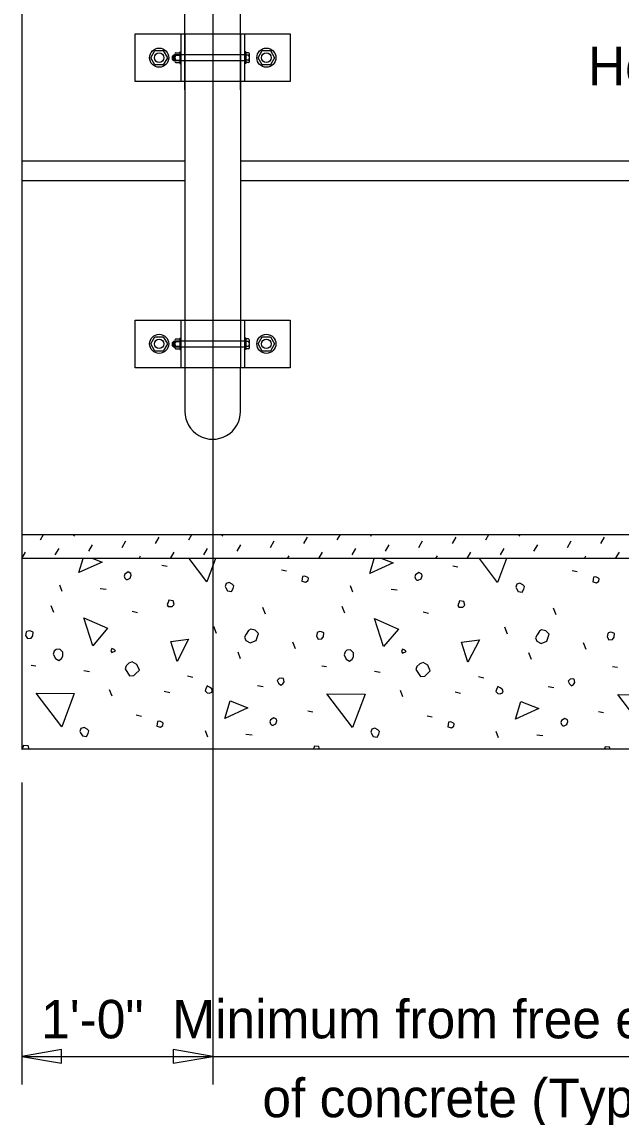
# Model space of a CAD drawing. Extents: x 0 to 41, y -96 to 25.
# Drawn here: x 4.32 to 7.46, y 9.59 to 15.33 of the extents above; entities that cross this region are included whole.
import ezdxf

# ---------------------------------------------------------------- set-up
doc = ezdxf.new("R2010")
doc.units = 0
for name, color, linetype in [('CL_Major', 7, 'Continuous'), ('Dimension', 7, 'Continuous'), ('Miscellaneous', 7, 'Continuous'), ('SteelMisc', 7, 'Continuous'), ('SteelMisc_h', 7, 'Continuous'), ('SupstrConc', 7, 'Continuous'), ('TextStructures', 7, 'Continuous')]:
    doc.layers.add(name, color=color, linetype=linetype)

msp = doc.modelspace()

# ---------------------------------------------------------------- linework, layer by layer
at = {"layer": 'CL_Major'}
msp.add_line((5.3237, 24.7173), (5.3237, 9.756), dxfattribs=at)
at = {"layer": 'Dimension'}
for p, q in [((4.3237, 11.3401), (4.3237, 9.756)), ((4.3238, 9.9041), (9.0982, 9.9041))]:
    msp.add_line(p, q, dxfattribs=at)
for points in [[(4.3238, 9.9041), (4.532, 9.8688), (4.532, 9.9394)], [(5.3238, 9.9042), (5.1155, 9.9395), (5.1155, 9.8689)]]:
    msp.add_lwpolyline(points, close=True, dxfattribs=at)
at = {"layer": 'Miscellaneous'}
for p, q in [((5.1162, 15.1316), (5.1162, 15.1437)), ((5.1219, 15.1316), (5.1219, 15.1437)), ((5.1162, 13.6316), (5.1162, 13.6437)), ((5.1219, 13.6316), (5.1219, 13.6437)), ((4.421, 12.6107), (4.437, 12.6385)), ((4.596, 12.6302), (4.6008, 12.6385)), ((5.1988, 12.6107), (5.2148, 12.6385)), ((5.3738, 12.6302), (5.3786, 12.6385)), ((5.9766, 12.6107), (5.9927, 12.6385)), ((6.1516, 12.6302), (6.1564, 12.6385)), ((6.7544, 12.6107), (6.7705, 12.6385)), ((6.9294, 12.6302), (6.9342, 12.6385)), ((4.6738, 12.5524), (4.6932, 12.586)), ((4.8488, 12.5718), (4.8682, 12.6054)), ((5.0238, 12.5913), (5.0432, 12.6249)), ((5.4516, 12.5524), (5.471, 12.586)), ((5.6266, 12.5718), (5.646, 12.6054)), ((5.8016, 12.5913), (5.821, 12.6249)), ((6.2294, 12.5524), (6.2488, 12.586)), ((6.4044, 12.5718), (6.4238, 12.6054)), ((6.5794, 12.5913), (6.5989, 12.6249)), ((7.0072, 12.5524), (7.0267, 12.586)), ((7.1822, 12.5718), (7.2017, 12.6054)), ((7.3572, 12.5913), (7.3767, 12.6249)), ((4.3237, 12.5135), (4.3432, 12.5471)), ((4.4987, 12.533), (4.5182, 12.5665)), ((4.9378, 12.5135), (4.946, 12.5276)), ((5.1016, 12.5135), (5.121, 12.5471)), ((5.2766, 12.533), (5.296, 12.5665)), ((5.7156, 12.5135), (5.7238, 12.5276)), ((5.8794, 12.5135), (5.8988, 12.5471)), ((6.0544, 12.533), (6.0738, 12.5665)), ((6.4934, 12.5135), (6.5016, 12.5276)), ((6.6572, 12.5135), (6.6766, 12.5471)), ((6.8322, 12.533), (6.8516, 12.5665)), ((7.2713, 12.5135), (7.2794, 12.5276)), ((7.435, 12.5135), (7.4545, 12.5471)), ((5.0576, 12.4782), (5.0841, 12.4728)), ((6.5814, 12.4746), (6.6079, 12.4693)), ((5.6833, 12.4534), (5.7099, 12.4481)), ((7.2072, 12.4499), (7.2337, 12.4446)), ((4.5343, 12.3403), (4.5219, 12.3739)), ((4.7341, 12.3562), (4.7659, 12.3526)), ((6.0581, 12.3367), (6.0457, 12.3703)), ((6.2579, 12.3526), (6.2897, 12.3491)), ((4.4919, 12.2307), (4.4777, 12.266)), ((4.902, 12.2377), (4.9303, 12.2307)), ((5.6003, 12.2218), (5.5861, 12.2572)), ((6.0157, 12.2271), (6.0015, 12.2625)), ((6.4258, 12.2342), (6.4541, 12.2271)), ((7.1241, 12.2183), (7.1099, 12.2536)), ((5.3439, 12.1211), (5.3298, 12.1564)), ((6.8677, 12.1175), (6.8536, 12.1529)), ((5.7576, 12.0397), (5.7434, 12.0751)), ((7.2814, 12.0362), (7.2673, 12.0716)), ((5.4694, 11.9885), (5.4571, 12.0221)), ((6.9933, 11.9849), (6.9809, 12.0185)), ((4.3717, 11.9549), (4.3964, 11.9514)), ((5.8955, 11.9514), (5.9202, 11.9478)), ((7.4193, 11.9478), (7.444, 11.9443)), ((4.6474, 11.9266), (4.6775, 11.9213)), ((5.1919, 11.8983), (5.2202, 11.8913)), ((6.1712, 11.9231), (6.2013, 11.9178)), ((6.7157, 11.8948), (6.744, 11.8877)), ((4.7959, 11.7923), (4.7835, 11.8258)), ((5.5578, 11.8471), (5.5879, 11.8418)), ((7.0816, 11.8435), (7.1117, 11.8382)), ((5.0699, 11.8188), (5.0982, 11.8117)), ((6.3197, 11.7887), (6.3074, 11.8223)), ((6.5937, 11.8152), (6.622, 11.8082)), ((4.3237, 11.7127), (4.3239, 11.7127)), ((5.8212, 11.7145), (5.8477, 11.7092)), ((7.345, 11.7109), (7.3716, 11.7056)), ((4.9232, 11.6933), (4.9497, 11.688)), ((6.447, 11.6897), (6.4735, 11.6844)), ((5.298, 11.5766), (5.2856, 11.6102)), ((6.8218, 11.5731), (6.8094, 11.6066)), ((5.4977, 11.5925), (5.5295, 11.589)), ((7.0215, 11.589), (7.0534, 11.5854))]:
    msp.add_line(p, q, dxfattribs=at)
for points in [[(4.6227, 12.4393), (4.6455, 12.5135)], [(4.6956, 12.5135), (4.7447, 12.4941), (4.6227, 12.4393)], [(5.2927, 12.3915), (5.2, 12.5135)], [(5.3383, 12.5135), (5.2927, 12.3915)], [(6.1465, 12.4357), (6.1704, 12.5135)], [(6.2105, 12.5135), (6.2685, 12.4905), (6.1465, 12.4357)], [(6.8165, 12.388), (6.7211, 12.5135)], [(6.8634, 12.5135), (6.8165, 12.388)], [(4.8702, 12.4039), (4.8772, 12.4039), (4.8914, 12.411), (4.8967, 12.4269), (4.8949, 12.4357), (4.8808, 12.4428), (4.8631, 12.4322), (4.8596, 12.4216), (4.8631, 12.411), (4.8702, 12.4039)], [(5.7912, 12.3951), (5.8106, 12.3898), (5.823, 12.3986), (5.8248, 12.411), (5.8212, 12.4145), (5.8071, 12.4216), (5.7947, 12.4198), (5.7929, 12.4074), (5.7912, 12.3951)], [(6.394, 12.4004), (6.4011, 12.4004), (6.4152, 12.4074), (6.4205, 12.4234), (6.4187, 12.4322), (6.4046, 12.4393), (6.3869, 12.4287), (6.3834, 12.418), (6.3869, 12.4074), (6.394, 12.4004)], [(7.315, 12.3915), (7.3344, 12.3862), (7.3468, 12.3951), (7.3486, 12.4074), (7.345, 12.411), (7.3309, 12.418), (7.3185, 12.4163), (7.3168, 12.4039), (7.315, 12.3915)], [(5.3917, 12.3597), (5.4005, 12.3438), (5.4217, 12.3403), (5.4306, 12.3562), (5.4341, 12.3703), (5.4252, 12.3792), (5.4093, 12.388), (5.3934, 12.3827), (5.3881, 12.3668), (5.3917, 12.3597)], [(6.9155, 12.3562), (6.9243, 12.3403), (6.9455, 12.3367), (6.9544, 12.3526), (6.9579, 12.3668), (6.9491, 12.3756), (6.9332, 12.3845), (6.9172, 12.3792), (6.9119, 12.3632), (6.9155, 12.3562)], [(5.0894, 12.2625), (5.1106, 12.2625), (5.1212, 12.2731), (5.1159, 12.2925), (5.0929, 12.2943), (5.0894, 12.2837), (5.0841, 12.2749), (5.0894, 12.2625), (5.0858, 12.266)], [(6.6132, 12.2589), (6.6344, 12.2589), (6.645, 12.2696), (6.6397, 12.289), (6.6167, 12.2908), (6.6132, 12.2802), (6.6079, 12.2713), (6.6132, 12.2589), (6.6097, 12.2625)], [(4.6952, 12.0557), (4.6474, 12.2024), (4.7729, 12.1476), (4.6952, 12.0557)], [(6.219, 12.0521), (6.1712, 12.1988), (6.2968, 12.144), (6.219, 12.0521)], [(4.3434, 12.1105), (4.3522, 12.0945), (4.3717, 12.0963), (4.3805, 12.1087), (4.3823, 12.1281), (4.3699, 12.1334), (4.3611, 12.1352), (4.3504, 12.1317), (4.3469, 12.1281), (4.3434, 12.1105)], [(5.4977, 12.0839), (5.5207, 12.0716), (5.5508, 12.0839), (5.5631, 12.1211), (5.5455, 12.1387), (5.5225, 12.144), (5.5119, 12.137), (5.4995, 12.1175), (5.4907, 12.1016), (5.4977, 12.0839)], [(5.8672, 12.1069), (5.876, 12.091), (5.8955, 12.0928), (5.9043, 12.1052), (5.9061, 12.1246), (5.8937, 12.1299), (5.8849, 12.1317), (5.8743, 12.1281), (5.8707, 12.1246), (5.8672, 12.1069)], [(7.0215, 12.0804), (7.0445, 12.068), (7.0746, 12.0804), (7.0869, 12.1175), (7.0693, 12.1352), (7.0463, 12.1405), (7.0357, 12.1334), (7.0233, 12.114), (7.0145, 12.0981), (7.0215, 12.0804)], [(7.391, 12.1034), (7.3998, 12.0875), (7.4193, 12.0892), (7.4281, 12.1016), (7.4299, 12.1211), (7.4175, 12.1264), (7.4087, 12.1281), (7.3981, 12.1246), (7.3945, 12.1211), (7.391, 12.1034)], [(5.1371, 11.9743), (5.1035, 12.0786), (5.1972, 12.091), (5.1371, 11.9743)], [(6.6609, 11.9708), (6.6273, 12.0751), (6.721, 12.0875), (6.6609, 11.9708)], [(4.4883, 12.0115), (4.4989, 11.9902), (4.5166, 11.9796), (4.5308, 11.9902), (4.5378, 12.0009), (4.5378, 12.0221), (4.5219, 12.038), (4.5025, 12.0362), (4.4936, 12.0274), (4.4883, 12.0115)], [(4.7942, 12.0203), (4.8136, 12.0291), (4.8065, 12.0362), (4.7942, 12.0415), (4.7889, 12.0291), (4.7942, 12.0203)], [(6.0121, 12.0079), (6.0228, 11.9867), (6.0404, 11.9761), (6.0546, 11.9867), (6.0616, 11.9973), (6.0616, 12.0185), (6.0457, 12.0344), (6.0263, 12.0327), (6.0174, 12.0238), (6.0121, 12.0079)], [(6.318, 12.0168), (6.3374, 12.0256), (6.3303, 12.0327), (6.318, 12.038), (6.3127, 12.0256), (6.318, 12.0168)], [(4.8649, 11.9354), (4.8878, 11.8983), (4.9108, 11.9001), (4.9197, 11.9089), (4.9391, 11.9284), (4.9267, 11.9584), (4.902, 11.9726), (4.8843, 11.9655), (4.8702, 11.9514), (4.8649, 11.9354)], [(6.3887, 11.9319), (6.4117, 11.8948), (6.4346, 11.8966), (6.4435, 11.9054), (6.4629, 11.9248), (6.4506, 11.9549), (6.4258, 11.969), (6.4081, 11.962), (6.394, 11.9478), (6.3887, 11.9319)], [(5.6692, 11.8594), (5.6798, 11.8488), (5.6904, 11.8559), (5.6975, 11.8665), (5.6939, 11.8842), (5.6851, 11.8859), (5.6727, 11.8842), (5.6621, 11.8736), (5.6692, 11.8594)], [(7.193, 11.8559), (7.2036, 11.8453), (7.2142, 11.8524), (7.2213, 11.863), (7.2178, 11.8806), (7.2089, 11.8824), (7.1965, 11.8806), (7.1859, 11.87), (7.193, 11.8559)], [(5.2944, 11.8099), (5.3068, 11.8082), (5.3192, 11.8135), (5.3227, 11.8241), (5.3174, 11.8329), (5.3068, 11.84), (5.2944, 11.8453), (5.2874, 11.8311), (5.2838, 11.8205), (5.2944, 11.8099)], [(6.8182, 11.8064), (6.8306, 11.8046), (6.843, 11.8099), (6.8465, 11.8205), (6.8412, 11.8294), (6.8306, 11.8365), (6.8182, 11.8418), (6.8112, 11.8276), (6.8076, 11.817), (6.8182, 11.8064)], [(4.5325, 11.6314), (4.3982, 11.8082), (4.5979, 11.8064), (4.5325, 11.6314)], [(6.0563, 11.6279), (5.922, 11.8046), (6.1217, 11.8029), (6.0563, 11.6279)], [(7.5802, 11.6243), (7.4458, 11.8011), (7.6456, 11.7993), (7.5802, 11.6243)], [(5.3864, 11.6756), (5.4146, 11.7675), (5.5083, 11.7304), (5.3864, 11.6756)], [(6.9102, 11.672), (6.9385, 11.764), (7.0321, 11.7269), (6.9102, 11.672)], [(5.031, 11.6349), (5.0505, 11.6296), (5.0629, 11.6385), (5.0646, 11.6508), (5.0611, 11.6544), (5.0469, 11.6614), (5.0346, 11.6597), (5.0328, 11.6473), (5.031, 11.6349)], [(5.6338, 11.6402), (5.6409, 11.6402), (5.6551, 11.6473), (5.6604, 11.6632), (5.6586, 11.672), (5.6445, 11.6791), (5.6268, 11.6685), (5.6232, 11.6579), (5.6268, 11.6473), (5.6338, 11.6402)], [(6.5549, 11.6314), (6.5743, 11.6261), (6.5867, 11.6349), (6.5884, 11.6473), (6.5849, 11.6508), (6.5708, 11.6579), (6.5584, 11.6561), (6.5566, 11.6438), (6.5549, 11.6314)], [(7.1577, 11.6367), (7.1647, 11.6367), (7.1789, 11.6438), (7.1842, 11.6597), (7.1824, 11.6685), (7.1683, 11.6756), (7.1506, 11.665), (7.1471, 11.6544), (7.1506, 11.6438), (7.1577, 11.6367)], [(4.6315, 11.5996), (4.6404, 11.5837), (4.6616, 11.5801), (4.6704, 11.596), (4.6739, 11.6102), (4.6651, 11.619), (4.6492, 11.6279), (4.6333, 11.6226), (4.628, 11.6066), (4.6315, 11.5996)], [(6.1553, 11.596), (6.1642, 11.5801), (6.1854, 11.5766), (6.1942, 11.5925), (6.1978, 11.6066), (6.1889, 11.6155), (6.173, 11.6243), (6.1571, 11.619), (6.1518, 11.6031), (6.1553, 11.596)], [(4.3609, 11.5135), (4.3557, 11.5324), (4.3328, 11.5342), (4.3292, 11.5236), (4.3239, 11.5147), (4.3245, 11.5135)], [(5.8838, 11.5135), (5.8796, 11.5289), (5.8566, 11.5306), (5.853, 11.52), (5.8491, 11.5135)], [(7.4066, 11.5135), (7.4034, 11.5253), (7.3804, 11.5271), (7.3769, 11.5165), (7.3751, 11.5135)]]:
    msp.add_lwpolyline(points, dxfattribs=at)
at = {"layer": 'SteelMisc'}
for p, q in [((5.1779, 14.97), (5.1779, 15.777)), ((5.4696, 14.97), (5.4696, 15.777)), ((4.9178, 15.2635), (5.7297, 15.2635)), ((4.9178, 15.0135), (4.9178, 15.2635)), ((5.1571, 15.2635), (5.1571, 15.0135)), ((5.4904, 15.2635), (5.4904, 15.0135)), ((5.7297, 15.2635), (5.7297, 15.0135)), ((5.1255, 15.1564), (5.1255, 15.1207)), ((5.1304, 15.1646), (5.1505, 15.1646)), ((5.1505, 15.1688), (5.1505, 15.1082)), ((5.1505, 15.1688), (5.1571, 15.1688)), ((5.1505, 15.1646), (5.1505, 15.1126)), ((5.4967, 15.1688), (5.4906, 15.1688)), ((5.4967, 15.1688), (5.4967, 15.1082)), ((5.5114, 15.1645), (5.4967, 15.1645)), ((5.5165, 15.1191), (5.5165, 15.158)), ((5.1134, 15.1465), (5.119, 15.1531)), ((5.1134, 15.1288), (5.1134, 15.1465)), ((5.1134, 15.1288), (5.119, 15.1232)), ((5.119, 15.1531), (5.1255, 15.1531)), ((5.119, 15.1232), (5.119, 15.1531)), ((5.119, 15.1232), (5.1255, 15.1232)), ((5.1302, 15.1515), (5.1505, 15.1515)), ((5.1302, 15.1256), (5.1505, 15.1256)), ((5.1305, 15.1126), (5.1505, 15.1126)), ((5.1505, 15.1082), (5.1571, 15.1082)), ((5.4967, 15.1082), (5.4906, 15.1082)), ((5.5115, 15.1515), (5.4967, 15.1515)), ((5.5115, 15.1255), (5.4967, 15.1255)), ((5.5114, 15.1125), (5.4967, 15.1125)), ((5.7297, 15.0135), (4.9178, 15.0135)), ((5.1779, 15.0135), (5.1779, 13.7635)), ((5.4696, 15.0135), (5.4696, 13.7635)), ((4.9178, 13.7635), (5.7297, 13.7635)), ((4.9178, 13.5135), (4.9178, 13.7635)), ((5.1571, 13.7635), (5.1571, 13.5135)), ((5.4904, 13.7635), (5.4904, 13.5135)), ((5.7297, 13.7635), (5.7297, 13.5135)), ((5.1304, 13.6646), (5.1505, 13.6646)), ((5.1505, 13.6688), (5.1505, 13.6082)), ((5.1505, 13.6688), (5.1571, 13.6688)), ((5.1505, 13.6646), (5.1505, 13.6126)), ((5.4967, 13.6688), (5.4906, 13.6688)), ((5.4967, 13.6688), (5.4967, 13.6082)), ((5.5114, 13.6645), (5.4967, 13.6645)), ((5.1134, 13.6465), (5.119, 13.6531)), ((5.1134, 13.6288), (5.1134, 13.6465)), ((5.1134, 13.6288), (5.119, 13.6232)), ((5.119, 13.6531), (5.1255, 13.6531)), ((5.119, 13.6232), (5.119, 13.6531)), ((5.119, 13.6232), (5.1255, 13.6232)), ((5.1255, 13.6564), (5.1255, 13.6207)), ((5.1302, 13.6515), (5.1505, 13.6515)), ((5.1302, 13.6256), (5.1505, 13.6256)), ((5.1305, 13.6126), (5.1505, 13.6126)), ((5.1505, 13.6082), (5.1571, 13.6082)), ((5.4967, 13.6082), (5.4906, 13.6082)), ((5.5115, 13.6515), (5.4967, 13.6515)), ((5.5115, 13.6255), (5.4967, 13.6255)), ((5.5114, 13.6125), (5.4967, 13.6125)), ((5.5165, 13.6191), (5.5165, 13.658)), ((5.7297, 13.5135), (4.9178, 13.5135)), ((5.1778, 13.5135), (5.1778, 13.2844)), ((5.4695, 13.2844), (5.4695, 13.5135))]:
    msp.add_line(p, q, dxfattribs=at)
for points in [[(5.0211, 15.1761), (5.0644, 15.1761), (5.0861, 15.1385), (5.0644, 15.101), (5.0211, 15.101), (4.9994, 15.1385)], [(5.5831, 15.1761), (5.6264, 15.1761), (5.6481, 15.1385), (5.6264, 15.101), (5.5831, 15.101), (5.5614, 15.1385)], [(5.0211, 13.6761), (5.0644, 13.6761), (5.0861, 13.6385), (5.0644, 13.601), (5.0211, 13.601), (4.9994, 13.6385)], [(5.5831, 13.6761), (5.6264, 13.6761), (5.6481, 13.6385), (5.6264, 13.601), (5.5831, 13.601), (5.5614, 13.6385)]]:
    msp.add_lwpolyline(points, close=True, dxfattribs=at)
for centre, radius in [((5.0428, 15.1385), 0.05), ((5.0428, 15.1385), 0.025), ((5.6047, 15.1385), 0.05), ((5.6047, 15.1385), 0.025), ((5.0428, 13.6385), 0.05), ((5.0428, 13.6385), 0.025), ((5.6047, 13.6385), 0.05), ((5.6047, 13.6385), 0.025)]:
    msp.add_circle(centre, radius, dxfattribs=at)
for centre, radius, start, end in [((5.1321, 15.158), 0.00674, 104.48908, 254.18889), ((5.5097, 15.158), 0.00673, 285.7823, 75.54039), ((5.145, 15.1385), 0.0196, 138.62797, 221.37203), ((5.1321, 15.1191), 0.00673, 105.7823, 255.54039), ((5.5097, 15.1191), 0.00674, 284.48908, 74.18889), ((5.4968, 15.1385), 0.0196, 318.62797, 41.37203), ((5.1321, 13.658), 0.00674, 104.48908, 254.18889), ((5.5097, 13.658), 0.00673, 285.7823, 75.54039), ((5.145, 13.6385), 0.0196, 138.62797, 221.37203), ((5.1321, 13.6191), 0.00673, 105.7823, 255.54039), ((5.5097, 13.6191), 0.00674, 284.48908, 74.18889), ((5.4968, 13.6385), 0.0196, 318.62797, 41.37203)]:
    msp.add_arc(centre, radius, start, end, dxfattribs=at)
msp.add_ellipse((5.3237, 13.2844), major_axis=(0, 0.1458), ratio=0.999499, start_param=1.570796, end_param=4.712389, dxfattribs=at)
at = {"layer": 'SteelMisc_h'}
for p, q in [((5.1779, 15.2635), (5.1779, 15.0135)), ((5.4696, 15.2635), (5.4696, 15.0135)), ((5.4904, 15.1531), (5.1255, 15.1531)), ((5.1255, 15.1232), (5.4904, 15.1232)), ((5.1779, 13.7635), (5.1779, 13.5135)), ((5.4696, 13.7635), (5.4696, 13.5135)), ((5.4904, 13.6531), (5.1255, 13.6531)), ((5.1255, 13.6232), (5.4904, 13.6232))]:
    msp.add_line(p, q, dxfattribs=at)
at = {"layer": 'SupstrConc'}
for p, q in [((4.3237, 15.6384), (4.3237, 11.5135)), ((4.3237, 14.5986), (5.1779, 14.5986)), ((5.4696, 14.5986), (15.1779, 14.5986)), ((4.3237, 14.4945), (5.1779, 14.4945)), ((5.4696, 14.4945), (15.1779, 14.4945)), ((4.3237, 12.6385), (16.7107, 12.6385)), ((16.7107, 12.5135), (4.3237, 12.5135)), ((16.7107, 11.5135), (4.3237, 11.5135))]:
    msp.add_line(p, q, dxfattribs=at)

# ---------------------------------------------------------------- texts
at = {"layer": 'TextStructures'}
for s, p in [('Hog Rings @ 2\'-0" Centers', (7.2903, 14.994)), ('1\'-0"  Minimum from free end ', (4.4248, 9.9985)), ('of concrete (Typ.)', (5.5841, 9.585))]:
    msp.add_text(s, height=0.2016, dxfattribs=at).set_placement(p)

doc.saveas('drawing.dxf')
